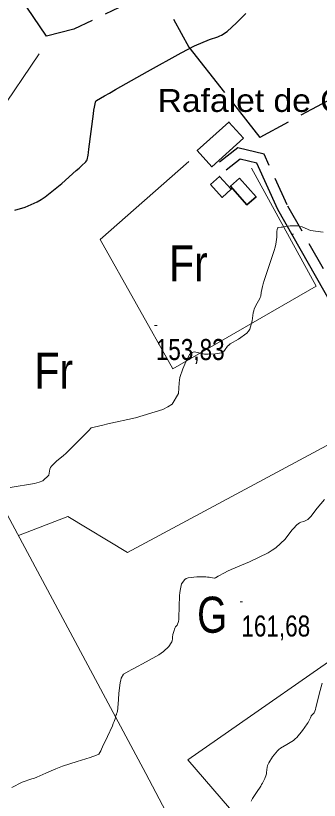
# Model space of a CAD drawing. Extents: x -807245 to 6129983, y -54972206 to 262146364.
# Drawn here: x 489594.4 to 489720.7, y 4382540.1 to 4382866.3 of the extents above; entities that cross this region are included whole.
import ezdxf
from ezdxf.enums import TextEntityAlignment as Align

# ---------------------------------------------------------------- set-up
doc = ezdxf.new("R2010")
doc.units = 0
doc.header["$LTSCALE"] = 4
doc.linetypes.add('LONG_DASHED', pattern=[7.5, 6, -1.5])
doc.linetypes.add('MEDIUM_DASHED', pattern=[4.5, 3, -1.5])
for name, color, linetype, lineweight in [('25', 7, 'LONG_DASHED', 25), ('27', 7, 'Continuous', 25), ('38', 7, 'Continuous', 25), ('39', 7, 'Continuous', 13), ('47', 7, 'Continuous', 35), ('51', 7, 'Continuous', 13), ('7', 7, 'Continuous', 13), ('8', 7, 'Continuous', 25), ('9', 7, 'Continuous', 13)]:
    doc.layers.add(name, color=color, linetype=linetype, lineweight=lineweight)
doc.layers.add('31', color=7, linetype='Continuous')
doc.layers.add('5', color=7, linetype='Continuous')

msp = doc.modelspace()

# ---------------------------------------------------------------- linework, layer by layer
at = {"layer": '25'}
msp.add_line((489666.4, 4382853.15), (489696, 4382815.71), dxfattribs=at)
for points in [[(489603.26, 4382963.5), (489632.6, 4382915.12), (489706.2, 4382948.35), (489712.04, 4382928.02), (489645.68, 4382891.27), (489666.4, 4382853.15)], [(489653.28, 4382877.3), (489618.63, 4382860.74), (489607.26, 4382857.8), (489596.49, 4382873.9), (489559.6, 4382855.19), (489552.12, 4382870.58)], [(489875.24, 4382848.88), (489836.7, 4382828.33), (489824.53, 4382820.95), (489800.86, 4382829.87), (489784.09, 4382861.78), (489760.66, 4382850.46), (489696, 4382815.71)]]:
    msp.add_lwpolyline(points, dxfattribs=at)
at = {"layer": '27'}
msp.add_spline([(491255.21, 4383970.03), (491244.34, 4383967.52), (491230.36, 4383957.66), (491230.81, 4383957.81), (491230.81, 4383957.81), (491220.15, 4383951.47), (491212.7, 4383943.01), (491205.06, 4383944.23), (491184.85, 4383957.71), (491152.82, 4383981.27), (491128.36, 4384004.58), (491128.29, 4384004.88), (491122.26, 4384021.39), (491095.75, 4384034.59), (491071.07, 4384059.32), (491064.71, 4384065.12)], degree=3, dxfattribs=at)
at = {"layer": '38', "linetype": 'MEDIUM_DASHED'}
msp.add_lwpolyline([(489740.22, 4382729.75), (489707.33, 4382787.67), (489697.79, 4382808.76), (489686.83, 4382811.42), (489679.25, 4382805.47)], dxfattribs=at)
at = {"layer": '38'}
msp.add_lwpolyline([(489803.9, 4382703.57), (489799.12, 4382701.6), (489765, 4382685.48), (489760.28, 4382687.9), (489741.7, 4382718.37), (489703.48, 4382785.71), (489694.72, 4382805.05), (489687.85, 4382806.72), (489681.92, 4382802.07)], dxfattribs=at)
at = {"layer": '39'}
msp.add_spline([(489117.55, 4382698.88), (489119.92, 4382672.68), (489122.01, 4382625.33), (489125.29, 4382585.13), (489126.65, 4382547.13), (489128.77, 4382508.18), (489130.39, 4382475.59), (489130.93, 4382447.55), (489133.21, 4382401.71), (489136.74, 4382363.61), (489144.72, 4382321.33), (489154.17, 4382280.07), (489166.23, 4382246.73), (489180.75, 4382210.53), (489205.22, 4382168.24), (489224.8, 4382133.94), (489257.72, 4382093.12), (489296.35, 4382054.96), (489327.82, 4382028.88), (489364.04, 4382002), (489408.28, 4381978.37), (489453.5, 4381958.06), (489487.73, 4381946.36), (489523.65, 4381936.12), (489563.73, 4381928.23), (489620.66, 4381920.7), (489680.32, 4381912.26), (489735.44, 4381905.59), (489799.91, 4381896.95), (489865.43, 4381887.81), (489926.74, 4381879.18), (489976.6, 4381873.08), (490039.39, 4381865.3), (490107.84, 4381856.38), (490175.25, 4381846.83), (490254.89, 4381836.5), (490348.33, 4381823.47), (490406.14, 4381813.57), (490409.06, 4381812.73)], degree=3, dxfattribs=at)
at = {"layer": '47'}
for points in [[(489689.18, 4382815.35), (489675.98, 4382803.53), (489669.94, 4382810.28), (489683.14, 4382822.1)], [(489675.5, 4382796.08), (489680.35, 4382790.76), (489684.09, 4382794.17), (489679.24, 4382799.49)], [(489687.59, 4382798.75), (489694.4, 4382790.94), (489690.61, 4382787.64), (489683.8, 4382795.45)]]:
    msp.add_lwpolyline(points, close=True, dxfattribs=at)
at = {"layer": '51'}
for p, q in [((489539.25, 4382754.69), (489604.19, 4382850.47)), ((489616.05, 4382658.06), (489595.57, 4382650.19))]:
    msp.add_line(p, q, dxfattribs=at)
for points in [[(489476.57, 4382870.31), (489563.62, 4382709.71), (489648.62, 4382551.3), (489679.14, 4382493.32), (489737.26, 4382390.87), (489799.11, 4382279.12), (489848.73, 4382191.34), (489888.75, 4382120.52), (489920.79, 4382133.89), (489922.21, 4382137.53)], [(489666.44, 4382805.71), (489629.5, 4382773.25), (489659.78, 4382719.54), (489719.48, 4382753.92), (489692.53, 4382802.98)], [(489756.4, 4382687.91), (489761.83, 4382679.7), (489802.89, 4382701.75), (489806.35, 4382701.6), (489822.36, 4382665.43), (489732.59, 4382641.56), (489746.05, 4382612.68), (489665.97, 4382556.93), (489711.14, 4382504.67), (489955.72, 4382603.47), (490079.97, 4382649.02), (490030.53, 4382721.36), (490182.61, 4382770.14), (490184.73, 4382769.06), (490210.75, 4382711.21)], [(489616.05, 4382658.06), (489640.91, 4382643.15), (489744.53, 4382698.74)]]:
    msp.add_lwpolyline(points, dxfattribs=at)
at = {"layer": '7'}
for p, q in [((489709.05, 4382775.45), (489710.05, 4382775.45)), ((489652.21, 4382737.53), (489653.21, 4382737.53)), ((489687.81, 4382622.59), (489688.81, 4382622.59))]:
    msp.add_line(p, q, dxfattribs=at)
at = {"layer": '8'}
msp.add_lwpolyline([(489594.11, 4382785.52), (489598.33, 4382786.75), (489603.38, 4382788.9), (489604.98, 4382789.88), (489606.68, 4382791.02), (489613.56, 4382796.53), (489619.64, 4382801.91), (489620.83, 4382802.98), (489621.8, 4382803.86), (489623.54, 4382805.54), (489623.84, 4382805.96), (489623.91, 4382806.05), (489623.98, 4382806.13), (489624.17, 4382806.35), (489624.52, 4382808.26), (489624.69, 4382809.41), (489624.88, 4382810.82), (489625.81, 4382818.16), (489626.76, 4382825.56), (489626.96, 4382827.01), (489627.14, 4382828.21), (489627.56, 4382830.35), (489627.79, 4382830.74), (489627.84, 4382830.82), (489627.89, 4382830.89), (489628.04, 4382831.07), (489631.37, 4382832.99), (489633.42, 4382834.16), (489635.96, 4382835.61), (489649.22, 4382843.15), (489663.2, 4382850.87), (489666.19, 4382852.44), (489668.8, 4382853.75), (489675.08, 4382856.4), (489678.5, 4382857.53), (489679.32, 4382857.88), (489680.08, 4382858.25), (489682.36, 4382859.71), (489686.28, 4382863.36), (489688.08, 4382865.1), (489690.19, 4382867.17)], dxfattribs=at)
at = {"layer": '9'}
for points in [[(489696.36, 4382749.66), (489696.61, 4382751.2), (489697.09, 4382753.78), (489697.4, 4382754.9), (489697.79, 4382756.21), (489699.86, 4382762.41), (489701.92, 4382768.7), (489702.3, 4382770.06), (489702.61, 4382771.26), (489703.07, 4382774.21), (489703.05, 4382775.85), (489703.05, 4382776.21), (489703.06, 4382776.55), (489703.14, 4382777.44), (489703.33, 4382777.96), (489703.41, 4382778.06), (489703.5, 4382778.15), (489703.92, 4382778.28), (489704.93, 4382778.38), (489705.4, 4382778.44), (489705.94, 4382778.51), (489708.54, 4382778.88), (489711.74, 4382778.88), (489712.65, 4382778.71), (489713.57, 4382778.48), (489717.01, 4382777.05), (489722.28, 4382776.28)], [(489592.16, 4382670.11), (489602.27, 4382671.79), (489604.19, 4382672.34), (489605.74, 4382672.92), (489608.16, 4382675.32), (489608.62, 4382677.81), (489608.93, 4382678.45), (489609.32, 4382679.07), (489611.4, 4382681.12), (489614.32, 4382683.51), (489615.24, 4382684.34), (489616.21, 4382685.25), (489620.12, 4382689.12), (489623.58, 4382692.66), (489624.26, 4382693.35), (489624.82, 4382693.91), (489625.86, 4382694.91), (489628.84, 4382695.68), (489630.62, 4382696.09), (489632.82, 4382696.6), (489644.25, 4382699.17), (489655.61, 4382702.63), (489657.77, 4382703.69), (489659.5, 4382704.8), (489662.18, 4382709.21), (489662.38, 4382713.65), (489662.55, 4382714.78), (489662.75, 4382715.87), (489663.9, 4382719.47), (489665.22, 4382722.4), (489665.54, 4382723.08), (489665.85, 4382723.69), (489666.78, 4382725.42), (489667.86, 4382726.35), (489668.26, 4382726.46), (489668.7, 4382726.51), (489670.63, 4382726.19), (489673.03, 4382725.67), (489673.76, 4382725.6), (489674.51, 4382725.56), (489677.48, 4382725.69), (489680.04, 4382726.19), (489680.53, 4382726.39), (489680.93, 4382726.61), (489681.61, 4382727.6), (489682.5, 4382728.96), (489683.04, 4382729.41), (489683.71, 4382729.88), (489687.15, 4382731.87), (489690.62, 4382734.36), (489691.3, 4382735.16), (489691.85, 4382736), (489692.83, 4382739.41), (489693.25, 4382742.79), (489693.45, 4382743.62), (489693.69, 4382744.39), (489694.85, 4382746.77), (489695.98, 4382748.7), (489696.19, 4382749.19), (489696.36, 4382749.66)], [(489637.05, 4382579.96), (489637.39, 4382584.55), (489637.91, 4382589.17), (489638.11, 4382590.12), (489638.33, 4382590.93), (489639.34, 4382592.63), (489641.49, 4382593.88), (489642.43, 4382594.4), (489643.52, 4382594.99), (489648.71, 4382597.72), (489653.91, 4382600.65), (489655.01, 4382601.35), (489655.96, 4382602.01), (489658.15, 4382604.03), (489659.13, 4382605.59), (489659.31, 4382605.96), (489659.45, 4382606.31), (489659.66, 4382607.38), (489659.72, 4382608.38), (489659.77, 4382608.7), (489659.83, 4382609.04), (489660.18, 4382610.38), (489660.66, 4382611.67), (489660.82, 4382611.96), (489660.97, 4382612.23), (489661.6, 4382612.98), (489662.15, 4382614.49), (489662.25, 4382615.24), (489662.33, 4382616.13), (489662.47, 4382620.52), (489662.6, 4382625.24), (489662.68, 4382626.33), (489662.79, 4382627.33), (489663.34, 4382630.17), (489664.76, 4382631.97), (489665.41, 4382632.32), (489666.17, 4382632.6), (489669.84, 4382633.06), (489673.51, 4382633), (489674.27, 4382632.96), (489674.92, 4382632.9), (489676.32, 4382632.59), (489677.08, 4382632.46), (489677.32, 4382632.51), (489677.57, 4382632.61), (489678.62, 4382633.28), (489681.3, 4382634.76), (489682.59, 4382635.37), (489684.12, 4382636.07), (489691.63, 4382639.3), (489699.44, 4382643.05), (489701.15, 4382644.08), (489702.68, 4382645.1), (489706.57, 4382648.75), (489708.91, 4382651.84), (489709.45, 4382652.52), (489709.94, 4382653.11), (489711.33, 4382654.61), (489712.45, 4382655.43), (489712.77, 4382655.59), (489713.1, 4382655.73), (489714.33, 4382656), (489715.95, 4382656.91), (489716.53, 4382657.45), (489717.16, 4382658.11), (489719.9, 4382661.52), (489722.85, 4382665.18)], [(489704.63, 4382561.77), (489707.28, 4382563.36), (489710, 4382565.04), (489710.71, 4382565.64), (489711.41, 4382566.3), (489713.78, 4382569.17), (489715.66, 4382571.94), (489716.04, 4382572.55), (489716.36, 4382573.08), (489717.03, 4382574.41), (489717.31, 4382575.13), (489717.39, 4382575.28), (489717.46, 4382575.41), (489717.72, 4382575.7), (489718, 4382575.91), (489718.08, 4382575.99), (489718.18, 4382576.08), (489718.54, 4382576.47), (489719.12, 4382577.95), (489719.35, 4382578.71), (489719.6, 4382579.64), (489720.73, 4382584.28), (489721.86, 4382588.87)], [(489592.87, 4382545.49), (489597.16, 4382547.74), (489601.16, 4382549.01), (489602.23, 4382549.4), (489603.28, 4382549.82), (489606.95, 4382551.46), (489611.11, 4382553.27), (489612.48, 4382553.79), (489613.94, 4382554.31), (489619.99, 4382556.25), (489625.43, 4382557.93), (489626.5, 4382558.29), (489627.38, 4382558.6), (489629, 4382559.33), (489629.81, 4382560.72), (489630.17, 4382561.44), (489630.6, 4382562.32), (489632.65, 4382566.72), (489634.65, 4382571.17), (489635.03, 4382572.09), (489635.35, 4382572.86), (489635.91, 4382574.49), (489636, 4382575.1), (489636.03, 4382575.23), (489636.06, 4382575.34), (489636.16, 4382575.61), (489636.3, 4382575.87), (489636.35, 4382575.97), (489636.4, 4382576.09), (489636.62, 4382576.64), (489636.88, 4382578.24), (489636.96, 4382579.02), (489637.05, 4382579.96)], [(489692.43, 4382539.78), (489692.67, 4382540.28), (489692.98, 4382540.85), (489694.6, 4382543.39), (489696.35, 4382546.08), (489696.75, 4382546.73), (489697.1, 4382547.34), (489698.05, 4382549.21), (489698.6, 4382550.76), (489698.7, 4382551.17), (489698.78, 4382551.58), (489698.89, 4382552.98), (489699.24, 4382554.6), (489699.46, 4382555.14), (489699.75, 4382555.73), (489701.26, 4382558.19), (489703.32, 4382560.65), (489703.96, 4382561.23), (489704.63, 4382561.77)]]:
    msp.add_lwpolyline(points, dxfattribs=at)

# ---------------------------------------------------------------- texts
at = {"layer": '31'}
for s, width, p in [('Fr', 0.85, (489666.29, 4382755.88)), ('Fr', 0.85, (489610.27, 4382711.23)), ('G', 0.8, (489676.16, 4382609.8))]:
    msp.add_text(s, height=15, dxfattribs=dict(at, width=width)).set_placement(p, align=Align.CENTER)
at = {"layer": '5', "width": 1.1}
msp.add_text('Rafalet de Ca l\'Amo en Juli"', height=9.5, dxfattribs=at).set_placement((489653.5, 4382826.3))
at = {"layer": '7', "width": 0.8}
for s, p in [('153,83', (489652.71, 4382723.16)), ('161,68', (489688.31, 4382608.22))]:
    msp.add_text(s, height=8.75, dxfattribs=at).set_placement(p)

doc.saveas('drawing.dxf')
